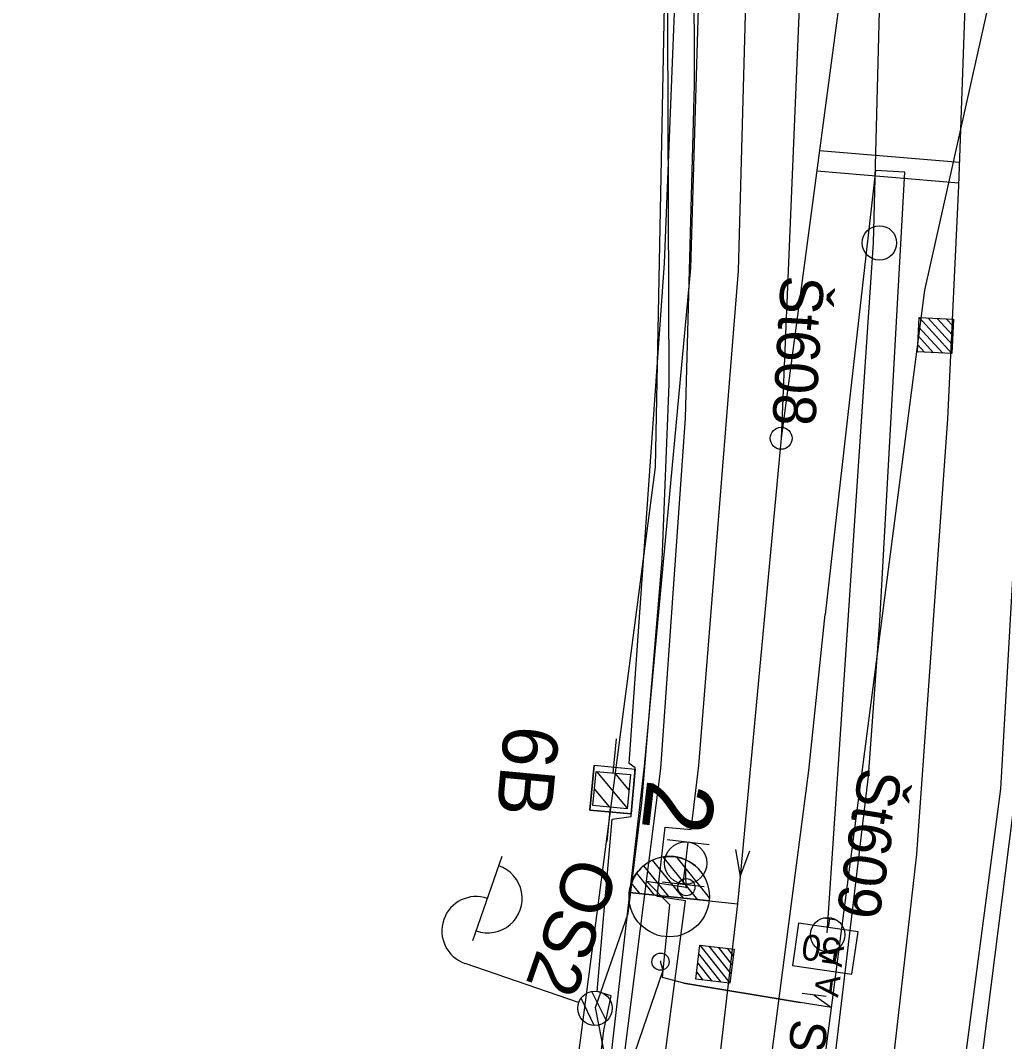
# Model space of a CAD drawing. Extents: x -545736 to -544888, y -1122892 to -1119128.
# Drawn here: x -545156.91 to -545128.27, y -1122602.4 to -1122572.69 of the extents above; entities that cross this region are included whole.
import ezdxf

# ---------------------------------------------------------------- set-up
doc = ezdxf.new("R2010")
doc.units = 0
for name, color, linetype in [('osvětlené plochy-hodnota-obrys', 7, 'Continuous'), ('Vrstva 1 - Koleje', 7, 'Continuous'), ('Vrstva 11 - Trakce', 7, 'Continuous'), ('Vrstva 12 - Trakce zaklady', 7, 'Continuous'), ('Vrstva 2 - Vyhybky', 7, 'Continuous'), ('Vrstva 25', 7, 'Continuous'), ('Vrstva 26', 7, 'Continuous'), ('Vrstva 27', 7, 'Continuous'), ('Vrstva 28 - zabzar', 7, 'Continuous'), ('Vrstva 3 - Lisy - Pocitaci body', 7, 'Continuous'), ('Vrstva 31', 7, 'Continuous'), ('Vrstva 32', 7, 'Continuous'), ('Vrstva 35', 7, 'Continuous'), ('Vrstva 4 - Teren - stezky - prechody - plochy', 7, 'Continuous'), ('Vrstva 43', 7, 'Continuous'), ('Vrstva 44', 7, 'Continuous'), ('Vrstva 5 - Vystroj', 7, 'Continuous'), ('Vrstva 6 - Navesti', 7, 'Continuous'), ('Vrstva 7 - Namezniky-vystroj', 7, 'Continuous')]:
    doc.layers.add(name, color=color, linetype=linetype)

msp = doc.modelspace()

# ---------------------------------------------------------------- linework, layer by layer
at = {"layer": 'osvětlené plochy-hodnota-obrys'}
for points in [[(-545134.488, -1122383.09), (-545138.436, -1122585.69), (-545142.696, -1122618.23), (-545150.566, -1122647.812), (-545144.37, -1122649.678)], [(-545136.491, -1122623.942), (-545134.432, -1122610.076), (-545134.432, -1122610.076), (-545130.588, -1122580.54), (-545121.507, -1122539.928), (-545114.985, -1122440.379), (-545107.655, -1122408.436), (-545092.05, -1122405.326)]]:
    msp.add_lwpolyline(points, dxfattribs=at)
at = {"layer": 'Vrstva 1 - Koleje'}
for points in [[(-545132.113, -1122493.06), (-545132.351, -1122502.539), (-545132.576, -1122511.557), (-545132.791, -1122520.224), (-545133.022, -1122529.75), (-545133.182, -1122536.046), (-545133.362, -1122542.952), (-545133.631, -1122553.198), (-545133.835, -1122560.954), (-545133.937, -1122564.862), (-545134.77, -1122584.848), (-545135.963, -1122597.599), (-545136.038, -1122598.395)], [(-545128.351, -1122532.879), (-545128.372, -1122533.679), (-545128.87, -1122552.83), (-545129.057, -1122559.925), (-545129.288, -1122568.437), (-545129.604, -1122577.497), (-545129.925, -1122584.285), (-545130.831, -1122596.948), (-545132.201, -1122608.983), (-545133.84, -1122619.134), (-545136.174, -1122630.305), (-545137.455, -1122635.497), (-545140.817, -1122647.245), (-545144.325, -1122657.562), (-545148.206, -1122667.467), (-545152.577, -1122677.284), (-545157.303, -1122686.734), (-545161.121, -1122693.673), (-545165.852, -1122701.579), (-545166.19, -1122702.117), (-545166.476, -1122702.566), (-545172.093, -1122711.045)], [(-545128.351, -1122532.879), (-545128.444, -1122533.674), (-545130.677, -1122552.693), (-545132.131, -1122565.025), (-545134.77, -1122584.848), (-545135.963, -1122597.599), (-545136.038, -1122598.395)], [(-545136.038, -1122598.395), (-545136.73, -1122604.306), (-545138.281, -1122615.318), (-545139.929, -1122624.144), (-545141.037, -1122629.184), (-545141.706, -1122631.984), (-545144.652, -1122642.826), (-545147.6, -1122651.963), (-545151.755, -1122663.049), (-545156.488, -1122673.941), (-545161.477, -1122684.006), (-545165.615, -1122691.531), (-545169.698, -1122698.363), (-545170.022, -1122698.884), (-545170.331, -1122699.382), (-545174.531, -1122705.823), (-545179.638, -1122713.064), (-545184.442, -1122719.349), (-545190.471, -1122726.844)]]:
    msp.add_lwpolyline(points, dxfattribs=at)
at = {"layer": 'Vrstva 11 - Trakce'}
for p, q in [((-545139.657, -1122594.596), (-545139.565, -1122593.59)), ((-545139.249, -1122595.604), (-545140.131, -1122594.542)), ((-545139.2, -1122595.076), (-545139.603, -1122594.591)), ((-545139.755, -1122595.581), (-545140.201, -1122595.044)), ((-545139.748, -1122595.578), (-545139.841, -1122596.578))]:
    msp.add_line(p, q, dxfattribs=at)
msp.add_lwpolyline([(-545140.247, -1122595.536), (-545140.155, -1122594.54), (-545139.159, -1122594.632), (-545139.251, -1122595.628)], close=True, dxfattribs=at)
at = {"layer": 'Vrstva 12 - Trakce zaklady'}
for p, q in [((-545140.214, -1122594.362), (-545139.019, -1122594.473)), ((-545140.335, -1122595.668), (-545139.14, -1122595.779))]:
    msp.add_line(p, q, dxfattribs=at)
for points in [[(-545140.335, -1122595.668), (-545140.214, -1122594.362), (-545139.019, -1122594.473), (-545139.14, -1122595.779), (-545140.335, -1122595.668)], [(-545140.214, -1122594.362), (-545140.214, -1122594.362), (-545140.335, -1122595.668), (-545140.335, -1122595.668)], [(-545139.14, -1122595.779), (-545139.14, -1122595.779), (-545139.019, -1122594.473), (-545139.019, -1122594.473)]]:
    msp.add_lwpolyline(points, dxfattribs=at)
at = {"layer": 'Vrstva 2 - Vyhybky'}
for p, q in [((-545137.195, -1122598.275), (-545138.2, -1122597.031)), ((-545136.854, -1122598.22), (-545137.808, -1122597.038)), ((-545138.039, -1122598.184), (-545138.765, -1122597.286)), ((-545137.617, -1122598.23), (-545138.51, -1122597.124)), ((-545138.461, -1122598.139), (-545138.971, -1122597.507)), ((-545138.883, -1122598.094), (-545139.123, -1122597.798)), ((-545136.857, -1122598.31), (-545139.185, -1122598.062)), ((-545139.185, -1122598.062), (-545136.857, -1122598.31)), ((-545136.857, -1122598.31), (-545136.857, -1122598.31)), ((-545136.856, -1122598.311), (-545136.038, -1122598.395))]:
    msp.add_line(p, q, dxfattribs=at)
for points in [[(-545133.937, -1122564.862), (-545134.77, -1122584.848)], [(-545132.131, -1122565.025), (-545134.77, -1122584.848), (-545135.963, -1122597.599), (-545136.038, -1122598.395)], [(-545136.097, -1122596.81), (-545135.963, -1122597.599), (-545135.685, -1122596.849)]]:
    msp.add_lwpolyline(points, dxfattribs=at)
for centre, radius in [((-545134.77, -1122584.848), 0.32), ((-545138.027, -1122598.185), 1.17)]:
    msp.add_circle(centre, radius, dxfattribs=at)
msp.add_arc((-545138.021, -1122598.186), 1.171, 353.9558, 173.9167, dxfattribs=at)
at = {"layer": 'Vrstva 25'}
for p, q in [((-545143.744, -1122599.465), (-545142.894, -1122597.008)), ((-545140.665, -1122601.271), (-545143.972, -1122600.127)), ((-545140.21, -1122601.933), (-545140.595, -1122601.142)), ((-545139.857, -1122601.803), (-545140.276, -1122600.942))]:
    msp.add_line(p, q, dxfattribs=at)
msp.add_circle((-545140.192, -1122601.434), 0.5, dxfattribs=at)
msp.add_circle((-545140.192, -1122601.434), 0.5, dxfattribs=at)
for centre, start, end in [((-545143.307, -1122598.241), 250.2255, 71.6306), ((-545143.646, -1122599.182), 70.928, 250.928)]:
    msp.add_arc(centre, 1, start, end, dxfattribs=at)
at = {"layer": 'Vrstva 26'}
for points in [[(-545140.173, -1122601.416), (-545139.225, -1122598.674), (-545138.828, -1122595.457), (-545138.236, -1122588.391), (-545138.033, -1122583.268), (-545138.077, -1122570.236), (-545138.229, -1122568.031), (-545138.22, -1122568.014)], [(-545146.276, -1122634.496), (-545146.167, -1122633.004), (-545145.098, -1122627.615), (-545142.797, -1122616.586), (-545139.816, -1122603.246), (-545140.173, -1122601.416), (-545140.192, -1122601.434)]]:
    msp.add_lwpolyline(points, dxfattribs=at)
at = {"layer": 'Vrstva 27'}
for p, q in [((-545137.527, -1122597.885), (-545137.533, -1122597.935)), ((-545138.277, -1122600.055), (-545138.283, -1122600.105))]:
    msp.add_line(p, q, dxfattribs=at)
for centre in [(-545137.53, -1122597.91), (-545138.28, -1122600.08)]:
    msp.add_circle(centre, 0.25, dxfattribs=at)
at = {"layer": 'Vrstva 28 - zabzar'}
for points in [[(-545139.49, -1122604.09), (-545138.69, -1122597.74), (-545138.27, -1122594.46), (-545137.55, -1122584.26), (-545137.29, -1122574.56), (-545137.31, -1122567.52), (-545137.85, -1122563.63), (-545139.06, -1122562.49), (-545138.96, -1122558.39), (-545139.24, -1122552.83), (-545138.1, -1122548.7), (-545137.31, -1122541.08), (-545136.56, -1122536.26), (-545136.54, -1122531.79), (-545136.53, -1122525.43), (-545137.3, -1122521.01), (-545137.26, -1122503.3), (-545136.84, -1122494.09)], [(-545133.81, -1122601.05), (-545133.3, -1122601.41), (-545134.22, -1122601.27), (-545137.6, -1122600.7), (-545138.22, -1122600.54), (-545138.2, -1122600.33), (-545138.01, -1122598.42), (-545138.69, -1122597.74), (-545137.53, -1122597.91), (-545137.55, -1122597.21)], [(-545138.2, -1122600.33), (-545138.28, -1122600.08)]]:
    msp.add_lwpolyline(points, dxfattribs=at)
at = {"layer": 'Vrstva 3 - Lisy - Pocitaci body'}
for p, q in [((-545130.757, -1122581.337), (-545129.802, -1122582.38)), ((-545130.493, -1122581.349), (-545129.79, -1122582.115)), ((-545130.227, -1122581.36), (-545129.779, -1122581.85)), ((-545129.963, -1122581.372), (-545129.767, -1122581.585)), ((-545130.78, -1122581.867), (-545130.332, -1122582.357)), ((-545130.769, -1122581.602), (-545130.066, -1122582.368)), ((-545130.792, -1122582.132), (-545130.596, -1122582.345)), ((-545138.09, -1122596.526), (-545136.866, -1122596.67)), ((-545137.622, -1122597.822), (-545137.478, -1122596.598)), ((-545138.234, -1122597.75), (-545137.01, -1122597.894)), ((-545137.134, -1122599.596), (-545136.259, -1122600.707)), ((-545136.871, -1122599.627), (-545136.228, -1122600.443)), ((-545136.607, -1122599.658), (-545136.196, -1122600.18)), ((-545136.344, -1122599.689), (-545136.165, -1122599.917)), ((-545137.165, -1122599.859), (-545136.522, -1122600.675)), ((-545137.197, -1122600.123), (-545136.786, -1122600.644)), ((-545137.228, -1122600.386), (-545137.049, -1122600.613))]:
    msp.add_line(p, q, dxfattribs=at)
for points in [[(-545129.758, -1122581.38), (-545129.802, -1122582.38), (-545130.801, -1122582.336), (-545130.757, -1122581.337)], [(-545136.141, -1122599.713), (-545136.259, -1122600.707), (-545137.252, -1122600.589), (-545137.134, -1122599.596)]]:
    msp.add_lwpolyline(points, close=True, dxfattribs=at)
msp.add_circle((-545137.55, -1122597.207), 0.616, dxfattribs=at)
at = {"layer": 'Vrstva 31'}
msp.add_lwpolyline([(-545139.49, -1122604.09), (-545138.69, -1122597.74), (-545138.27, -1122594.46), (-545137.55, -1122584.26), (-545137.29, -1122574.56), (-545137.31, -1122567.52), (-545137.85, -1122563.63), (-545139.06, -1122562.49), (-545139.24, -1122552.83), (-545138.1, -1122548.7), (-545137.31, -1122541.08), (-545136.56, -1122536.26), (-545136.53, -1122525.43), (-545137.3, -1122521.01), (-545137.26, -1122503.3), (-545136.84, -1122494.09)], dxfattribs=at)
at = {"layer": 'Vrstva 32'}
msp.add_lwpolyline([(-545139.49, -1122604.09), (-545138.2, -1122600.33), (-545138.01, -1122598.42), (-545138.69, -1122597.74), (-545138.27, -1122594.46), (-545137.55, -1122584.26), (-545137.29, -1122574.56), (-545137.31, -1122567.52), (-545137.85, -1122563.63), (-545139.06, -1122562.49), (-545138.96, -1122558.39), (-545139.24, -1122552.83), (-545138.1, -1122548.7), (-545137.31, -1122541.08), (-545136.56, -1122536.26), (-545136.53, -1122525.43), (-545137.3, -1122521.01), (-545137.26, -1122503.3), (-545136.84, -1122494.09)], dxfattribs=at)
msp.add_lwpolyline([(-545139.49, -1122604.09), (-545138.2, -1122600.33), (-545138.01, -1122598.42), (-545138.69, -1122597.74), (-545138.27, -1122594.46), (-545137.55, -1122584.26), (-545137.29, -1122574.56), (-545137.31, -1122567.52), (-545137.85, -1122563.63), (-545139.06, -1122562.49), (-545138.96, -1122558.39), (-545139.24, -1122552.83), (-545138.1, -1122548.7), (-545137.31, -1122541.08), (-545136.56, -1122536.26), (-545136.53, -1122525.43), (-545137.3, -1122521.01), (-545137.26, -1122503.3), (-545136.84, -1122494.09)], dxfattribs=at)
at = {"layer": 'Vrstva 35'}
msp.add_line((-545137.6, -1122600.7), (-545134.22, -1122601.27), dxfattribs=at)
at = {"layer": 'Vrstva 4 - Teren - stezky - prechody - plochy'}
for points in [[(-545191.629, -1122723.588), (-545190.606, -1122724.4), (-545183.082, -1122715.247), (-545174.471, -1122703.078), (-545169.188, -1122694.668), (-545163.388, -1122684.3), (-545157.763, -1122672.946), (-545152.235, -1122660.118), (-545147.809, -1122647.698), (-545144.117, -1122635.247), (-545141.561, -1122624.265), (-545139.354, -1122611.942), (-545137.55, -1122598.304), (-545138.381, -1122598.177), (-545138.144, -1122596.165), (-545137.394, -1122596.23), (-545137.164, -1122594.37), (-545136.011, -1122579.974), (-545135.245, -1122551.924), (-545134.376, -1122521.14), (-545133.892, -1122501.709), (-545133.405, -1122481.658)], [(-545140.685, -1122611.253), (-545138.752, -1122594.386), (-545137.402, -1122579.893), (-545136.844, -1122561.129), (-545136.511, -1122551.767), (-545135.87, -1122521.211), (-545135.812, -1122519.734), (-545135.589, -1122501.439), (-545134.927, -1122481.492), (-545133.405, -1122481.658)], [(-545141.024, -1122611.09), (-545139.933, -1122602.085), (-545139.716, -1122601.069), (-545140.128, -1122600.945), (-545139.688, -1122595.933), (-545139.138, -1122595.855), (-545139.019, -1122594.44), (-545139.197, -1122594.314), (-545138.162, -1122579.754), (-545137.734, -1122569.04), (-545138.855, -1122568.556), (-545138.807, -1122567.496), (-545137.462, -1122567.077), (-545137.179, -1122561.067), (-545136.824, -1122551.814), (-545135.969, -1122521.336), (-545135.87, -1122521.211), (-545135.812, -1122519.734), (-545135.964, -1122519.738), (-545135.589, -1122501.439), (-545135.812, -1122519.734)], [(-545143.646, -1122627.169), (-545143.029, -1122623.952), (-545140.685, -1122611.253), (-545138.752, -1122594.386), (-545137.402, -1122579.893), (-545136.844, -1122561.129), (-545136.511, -1122551.767), (-545135.87, -1122521.211)], [(-545188.115, -1122726.499), (-545186.816, -1122727.626), (-545179.153, -1122718.162), (-545170.497, -1122705.864), (-545165.086, -1122697.266), (-545159.078, -1122686.625), (-545153.254, -1122674.874), (-545147.771, -1122662.012), (-545143.139, -1122649.187), (-545139.43, -1122636.663), (-545136.752, -1122625.534), (-545134.412, -1122613.056), (-545132.223, -1122594.677), (-545131.9, -1122590.16), (-545131.166, -1122577.107), (-545132.023, -1122577.056), (-545133.492, -1122589.979)], [(-545186.378, -1122732.723), (-545176.423, -1122720.342), (-545167.539, -1122708.042), (-545161.897, -1122699.343), (-545155.785, -1122688.417), (-545149.851, -1122676.524), (-545144.387, -1122663.629), (-545139.443, -1122650.543), (-545135.826, -1122637.855), (-545133.045, -1122626.386), (-545130.874, -1122614.091), (-545128.38, -1122595.049), (-545127.699, -1122583.15), (-545127.21, -1122582.485)], [(-545186.002, -1122733.066), (-545175.816, -1122720.349), (-545167.024, -1122708.373), (-545161.453, -1122699.562), (-545155.318, -1122688.663), (-545149.336, -1122676.689), (-545143.889, -1122663.732), (-545138.985, -1122650.646), (-545135.373, -1122637.73), (-545132.645, -1122626.338), (-545130.342, -1122614.15), (-545127.919, -1122594.969), (-545127.21, -1122582.485)], [(-545188.115, -1122726.499), (-545180.687, -1122717.034), (-545171.997, -1122704.893), (-545166.551, -1122696.278), (-545160.616, -1122685.761), (-545154.913, -1122674.139), (-545149.454, -1122661.322), (-545144.857, -1122648.564), (-545141.182, -1122636.064), (-545138.489, -1122625.035), (-545136.341, -1122612.76), (-545133.964, -1122594.516), (-545133.492, -1122589.979)]]:
    msp.add_lwpolyline(points, dxfattribs=at)
at = {"layer": 'Vrstva 43'}
for centre in [(-545131.909, -1122579.161), (-545133.418, -1122599.295)]:
    msp.add_circle(centre, 0.5, dxfattribs=at)
at = {"layer": 'Vrstva 44'}
msp.add_lwpolyline([(-545133.427, -1122599.241), (-545132.083, -1122579.16), (-545130.845, -1122531.562), (-545130.119, -1122502.202), (-545130.021, -1122501.998), (-545129.768, -1122502.059), (-545120.639, -1122502.325), (-545120.437, -1122502.27), (-545120.505, -1122501.979), (-545119.331, -1122472.539), (-545116.186, -1122445.902), (-545109.415, -1122409.043)], dxfattribs=at)
at = {"layer": 'Vrstva 5 - Vystroj'}
for p, q in [((-545133.539, -1122598.803), (-545133.158, -1122598.856)), ((-545133.363, -1122598.833), (-545133.398, -1122599.08))]:
    msp.add_line(p, q, dxfattribs=at)
msp.add_lwpolyline([(-545132.532, -1122599.205), (-545134.264, -1122598.956), (-545134.442, -1122600.193), (-545132.71, -1122600.442)], close=True, dxfattribs=at)
at = {"layer": 'Vrstva 6 - Navesti'}
msp.add_line((-545133.463, -1122601.092), (-545134.157, -1122601.008), dxfattribs=at)
at = {"layer": 'Vrstva 7 - Namezniky-vystroj'}
for p, q in [((-545133.655, -1122576.471), (-545129.58, -1122576.813)), ((-545133.734, -1122577.067), (-545129.601, -1122577.413))]:
    msp.add_line(p, q, dxfattribs=at)

# ---------------------------------------------------------------- texts
at = {"layer": 'Vrstva 11 - Trakce'}
msp.add_text('6B', height=1.6, rotation=264.7067, dxfattribs=at).set_placement((-545142.817, -1122593.161))
at = {"layer": 'Vrstva 2 - Vyhybky'}
msp.add_text('2', height=2, rotation=263.3042, dxfattribs=at).set_placement((-545138.659, -1122594.736))
at = {"layer": 'Vrstva 25'}
msp.add_text('OS2', height=1.5, rotation=250.928, dxfattribs=at).set_placement((-545140.905, -1122596.939))
at = {"layer": 'Vrstva 43'}
for s, rotation, p in [('Št608', 266.5992, (-545134.769, -1122580.089)), ('Št609', 260.9548, (-545132.48, -1122594.392))]:
    msp.add_text(s, height=1.25, rotation=rotation, dxfattribs=at).set_placement(p)
at = {"layer": 'Vrstva 5 - Vystroj'}
msp.add_text('50', height=0.75, rotation=171.8148, dxfattribs=at).set_placement((-545133.007, -1122599.42))
at = {"layer": 'Vrstva 6 - Navesti'}
for s, height, rotation, p in [('A A ', 0.7, 83.1275, (-545133.115, -1122601.134)), ('Se6', 1.05, 263.5665, (-545134.453, -1122601.72))]:
    msp.add_text(s, height=height, rotation=rotation, dxfattribs=at).set_placement(p)

doc.saveas('drawing.dxf')
